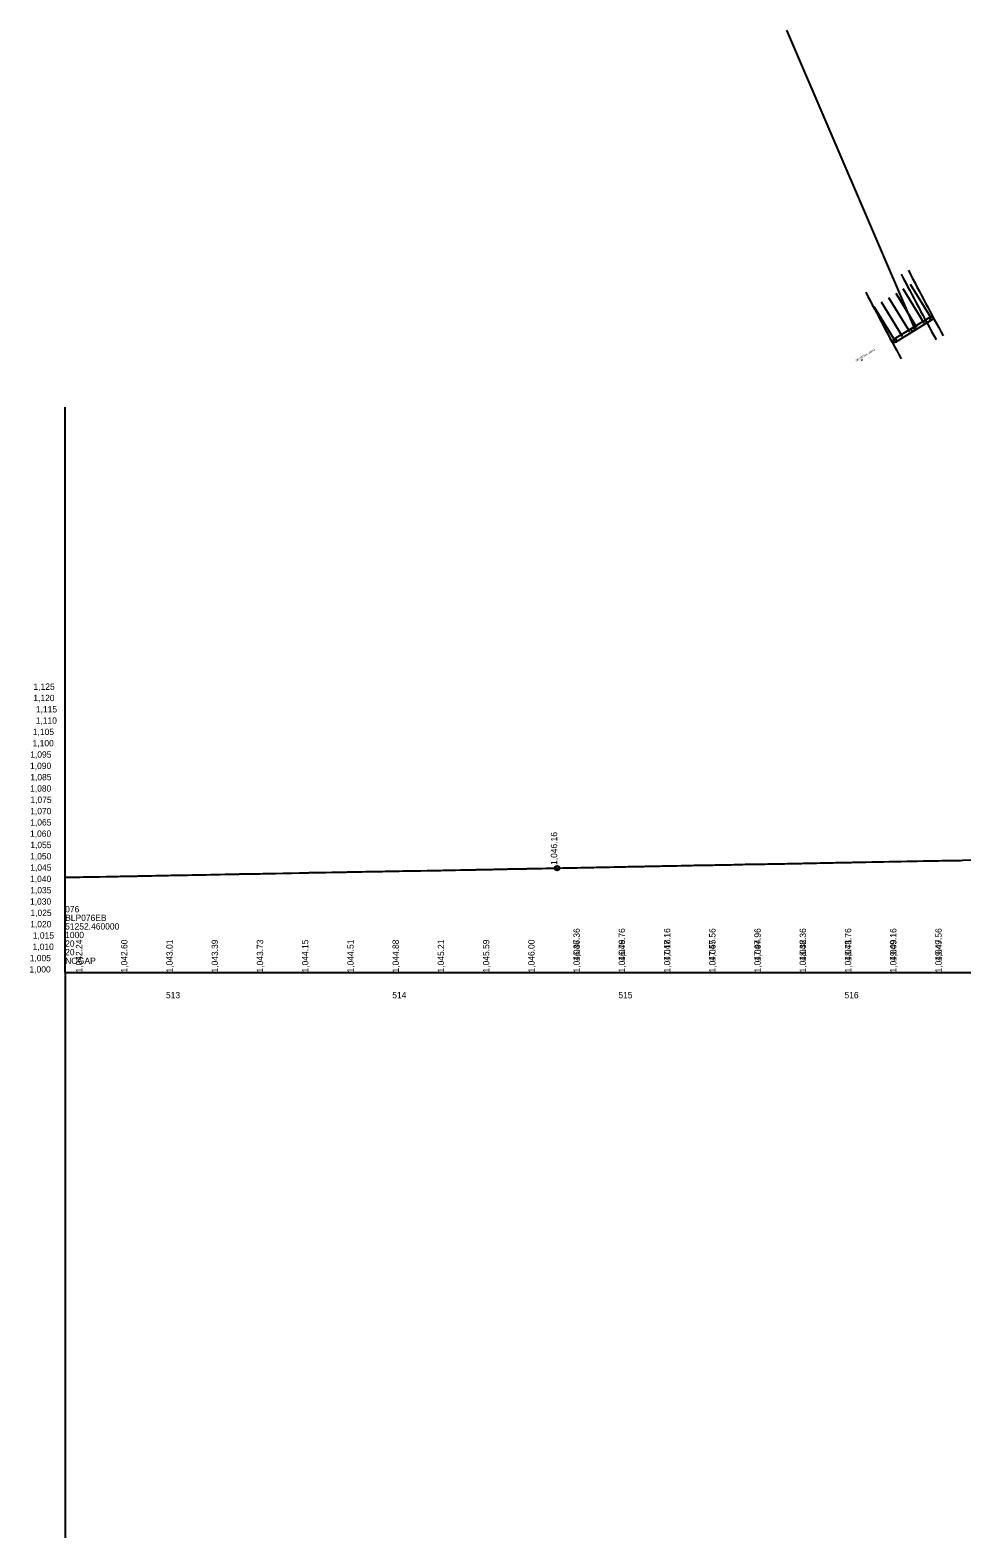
# Model space of a CAD drawing. Extents: x 2241514 to 2245530, y 509521 to 510188.
# Drawn here: x 2241514 to 2241926, y 509521 to 510188 of the extents above; entities that cross this region are included whole.
import ezdxf

# ---------------------------------------------------------------- set-up
doc = ezdxf.new("R2010")
doc.units = 0
for name, color, linetype in [('Default', 7, 'Continuous'), ('GK_Cells', 7, 'Continuous'), ('PF_P_Grade_Line', 7, 'Continuous'), ('PF_P_Sta_Elev_Text', 7, 'Continuous'), ('PF_P_Text', 7, 'Continuous'), ('PF_X_Ground_Line', 7, 'Continuous'), ('PF_X_Text', 7, 'Continuous'), ('SC_Scratch3', 7, 'Continuous')]:
    doc.layers.add(name, color=color, linetype=linetype)

msp = doc.modelspace()

# ---------------------------------------------------------------- linework, layer by layer
at = {"layer": 'GK_Cells'}
for q in [(2241529.6, 510021.03), (2245529.6, 509771.03), (2241529.6, 509521.03)]:
    msp.add_line((2241529.6, 509771.03), q, dxfattribs=at)
at = {"layer": 'PF_P_Grade_Line'}
msp.add_line((2241747.14, 509817.19), (2241977.14, 509821.8), dxfattribs=at)
at = {"layer": 'PF_P_Text'}
msp.add_circle((2241747.14, 509817.19), 1, dxfattribs=at)
at = {"layer": 'PF_X_Ground_Line'}
for points in [[(2241815.81, 509818.56), (2241816.09, 509818.57), (2241816.97, 509818.58), (2241818.02, 509818.6), (2241818.39, 509818.6), (2241818.68, 509818.61), (2241819.78, 509818.63), (2241821.49, 509818.66), (2241822.29, 509818.68), (2241823.25, 509818.71), (2241824, 509818.72), (2241825.43, 509818.76), (2241825.9, 509818.78), (2241826.36, 509818.79), (2241827.22, 509818.82), (2241828.1, 509818.84), (2241829.17, 509818.86), (2241830.27, 509818.88), (2241830.39, 509818.88), (2241831.63, 509818.9), (2241832.85, 509818.91), (2241833.66, 509818.92), (2241836.12, 509818.96), (2241836.12, 509818.96), (2241836.12, 509818.96), (2241838.15, 509818.99), (2241838.88, 509819), (2241840.31, 509819.02), (2241842.72, 509819.06), (2241842.74, 509819.06), (2241842.74, 509819.06), (2241842.79, 509819.06), (2241845.09, 509819.11), (2241845.38, 509819.12), (2241846.11, 509819.13), (2241847.26, 509819.16), (2241847.61, 509819.16), (2241849.03, 509819.18), (2241849.11, 509819.18), (2241850.08, 509819.2), (2241850.47, 509819.2), (2241852.67, 509819.25), (2241852.98, 509819.26), (2241853.23, 509819.27), (2241855.15, 509819.31), (2241856.05, 509819.33), (2241856.2, 509819.34), (2241856.7, 509819.35), (2241857.85, 509819.37), (2241858.35, 509819.38), (2241859.24, 509819.4), (2241860.23, 509819.42), (2241860.63, 509819.43), (2241860.87, 509819.43), (2241861.78, 509819.45), (2241863.4, 509819.48), (2241864.08, 509819.49), (2241864.36, 509819.5), (2241866.5, 509819.54), (2241866.63, 509819.55), (2241867.07, 509819.55), (2241868.12, 509819.57), (2241868.74, 509819.58), (2241869.13, 509819.58), (2241870.34, 509819.61), (2241870.83, 509819.62), (2241871.99, 509819.64), (2241872.4, 509819.65), (2241873.36, 509819.67), (2241873.64, 509819.68), (2241874.11, 509819.69), (2241876.86, 509819.74), (2241877.27, 509819.75), (2241877.86, 509819.77), (2241879.96, 509819.81), (2241881.06, 509819.83), (2241881.23, 509819.83), (2241881.45, 509819.84), (2241883.03, 509819.87), (2241883.68, 509819.88), (2241886.3, 509819.93), (2241886.32, 509819.93), (2241886.38, 509819.93), (2241888.9, 509819.99), (2241890.98, 509820.03), (2241891.46, 509820.03), (2241891.47, 509820.03), (2241891.47, 509820.03), (2241893.97, 509820.07), (2241894.03, 509820.07), (2241894.11, 509820.07), (2241894.31, 509820.08), (2241895.41, 509820.09), (2241895.95, 509820.1), (2241897.31, 509820.12), (2241899.01, 509820.16), (2241899.17, 509820.16), (2241899.28, 509820.17), (2241901.78, 509820.21), (2241902.1, 509820.22), (2241903.4, 509820.25)], [(2241903.4, 509820.25), (2241905.1, 509820.29), (2241905.74, 509820.31), (2241906.32, 509820.32), (2241909.11, 509820.36), (2241909.35, 509820.36), (2241909.59, 509820.37), (2241910.59, 509820.38), (2241911.83, 509820.4), (2241912.81, 509820.42), (2241913.47, 509820.43), (2241915.08, 509820.46), (2241915.75, 509820.48), (2241917.27, 509820.51), (2241918.49, 509820.53), (2241919.69, 509820.54), (2241920.1, 509820.55), (2241921.51, 509820.56), (2241922.26, 509820.56), (2241922.33, 509820.56), (2241923.94, 509820.59), (2241925.59, 509820.63), (2241926.5, 509820.66)], [(2241529.6, 509813.15), (2241530.14, 509813.15), (2241530.65, 509813.16), (2241531.71, 509813.18), (2241532.24, 509813.18), (2241533.72, 509813.21), (2241533.79, 509813.21), (2241535.74, 509813.25), (2241536.14, 509813.26), (2241537.57, 509813.28), (2241539.1, 509813.3), (2241540.88, 509813.32), (2241543.43, 509813.38), (2241544.78, 509813.4), (2241547.55, 509813.45), (2241548.19, 509813.46), (2241548.91, 509813.47), (2241549.21, 509813.48), (2241550.75, 509813.52), (2241551.53, 509813.53), (2241553.06, 509813.56), (2241553.91, 509813.58), (2241554.47, 509813.59), (2241555.36, 509813.61), (2241557.25, 509813.63), (2241558.15, 509813.65), (2241558.31, 509813.65), (2241558.47, 509813.66), (2241560, 509813.68), (2241561.02, 509813.69), (2241561.44, 509813.7), (2241562.08, 509813.71), (2241563.43, 509813.74), (2241564.49, 509813.77), (2241565.66, 509813.8), (2241565.83, 509813.8), (2241566.04, 509813.81), (2241566.81, 509813.82), (2241567.72, 509813.85), (2241569.69, 509813.9), (2241570.32, 509813.91), (2241571.44, 509813.94), (2241572.4, 509813.96), (2241573.64, 509813.98), (2241575.03, 509814), (2241575.29, 509814), (2241576.38, 509814.03), (2241577.61, 509814.05), (2241577.94, 509814.06), (2241579.21, 509814.08), (2241581.31, 509814.11), (2241581.69, 509814.11), (2241582.48, 509814.12), (2241583.09, 509814.13), (2241583.73, 509814.14), (2241585.77, 509814.17), (2241586.61, 509814.18), (2241587.17, 509814.19), (2241587.85, 509814.2), (2241589.77, 509814.24), (2241590.4, 509814.25), (2241591.96, 509814.29), (2241594.01, 509814.34), (2241594.76, 509814.36), (2241595.27, 509814.38), (2241597.02, 509814.42), (2241597.38, 509814.43), (2241598.2, 509814.44), (2241600.39, 509814.48), (2241600.91, 509814.49), (2241601.58, 509814.5), (2241601.89, 509814.5), (2241602.84, 509814.52), (2241603.02, 509814.53), (2241603.9, 509814.54), (2241605.84, 509814.58), (2241606.45, 509814.59), (2241606.75, 509814.6), (2241607.55, 509814.61), (2241609.43, 509814.64), (2241610.16, 509814.63), (2241610.32, 509814.63), (2241610.82, 509814.64), (2241613.66, 509814.66), (2241615.66, 509814.73), (2241617.04, 509814.76), (2241617.85, 509814.77), (2241618.15, 509814.78), (2241620.48, 509814.82), (2241621.94, 509814.85), (2241622.55, 509814.87), (2241625.85, 509814.94), (2241625.96, 509814.94), (2241625.97, 509814.94), (2241626.01, 509814.94), (2241626.04, 509814.95), (2241627.36, 509814.98), (2241628.84, 509815.01), (2241629.33, 509815.01), (2241629.43, 509815.02), (2241629.58, 509815.02)], [(2241629.58, 509815.02), (2241629.74, 509815.02), (2241633.28, 509815.09), (2241633.46, 509815.1), (2241635.01, 509815.13), (2241637.08, 509815.18), (2241637.54, 509815.19), (2241639.14, 509815.23), (2241640.68, 509815.26), (2241641.84, 509815.29), (2241643.68, 509815.31), (2241644.67, 509815.33), (2241644.91, 509815.33), (2241647.45, 509815.35), (2241647.62, 509815.35), (2241647.77, 509815.35), (2241647.98, 509815.36), (2241648.45, 509815.37), (2241649.81, 509815.38), (2241651.35, 509815.41), (2241651.55, 509815.42), (2241652.04, 509815.43), (2241653.49, 509815.46), (2241653.8, 509815.47), (2241654.5, 509815.49), (2241656.22, 509815.53), (2241657.11, 509815.54), (2241657.89, 509815.56), (2241658.08, 509815.56), (2241659.98, 509815.59), (2241660.14, 509815.6), (2241660.54, 509815.61), (2241660.92, 509815.61), (2241662.47, 509815.63), (2241663.33, 509815.64), (2241664.29, 509815.66), (2241665.55, 509815.68), (2241666.09, 509815.69), (2241667.8, 509815.72), (2241668.43, 509815.73), (2241669.88, 509815.76), (2241671.03, 509815.79), (2241672.14, 509815.81), (2241672.56, 509815.82), (2241673.22, 509815.83), (2241674.32, 509815.86), (2241674.94, 509815.87), (2241675.48, 509815.88), (2241676.69, 509815.9), (2241676.72, 509815.9), (2241676.77, 509815.9), (2241677.25, 509815.91), (2241678.86, 509815.93), (2241679, 509815.94), (2241680.92, 509815.96), (2241680.96, 509815.96), (2241680.96, 509815.96), (2241682.77, 509815.98), (2241685.1, 509816.01), (2241685.14, 509816.01), (2241685.16, 509816.01), (2241686.35, 509816.04), (2241686.39, 509816.04), (2241686.43, 509816.04), (2241686.71, 509816.05), (2241689.71, 509816.12), (2241690.39, 509816.12), (2241691.3, 509816.13), (2241692.75, 509816.14), (2241693.15, 509816.15), (2241693.36, 509816.15), (2241695.44, 509816.2), (2241695.69, 509816.2), (2241696.67, 509816.23), (2241697.63, 509816.25), (2241697.94, 509816.26), (2241700.02, 509816.31), (2241700.66, 509816.33), (2241700.86, 509816.33), (2241702.22, 509816.36), (2241702.23, 509816.36), (2241702.23, 509816.36), (2241702.23, 509816.36), (2241704.37, 509816.39), (2241706.37, 509816.42), (2241706.5, 509816.42), (2241706.58, 509816.42), (2241706.89, 509816.43), (2241709.58, 509816.47), (2241710.61, 509816.5), (2241710.96, 509816.5), (2241711.33, 509816.51), (2241713.29, 509816.55), (2241713.44, 509816.56), (2241714.89, 509816.58), (2241715.3, 509816.58), (2241715.5, 509816.59), (2241716.96, 509816.62), (2241717.97, 509816.64), (2241718.55, 509816.65), (2241719.34, 509816.67)], [(2241719.34, 509816.67), (2241720.46, 509816.7), (2241721.47, 509816.73), (2241722.2, 509816.74), (2241722.97, 509816.75), (2241723.34, 509816.76), (2241724.17, 509816.78), (2241724.89, 509816.8), (2241725.46, 509816.81), (2241726.82, 509816.82), (2241727.96, 509816.84), (2241728.26, 509816.84), (2241729.91, 509816.87), (2241730.88, 509816.89), (2241732.53, 509816.92), (2241732.68, 509816.93), (2241733.66, 509816.95), (2241733.67, 509816.95), (2241733.82, 509816.96), (2241737.61, 509817.04), (2241737.68, 509817.05), (2241737.8, 509817.05), (2241739.13, 509817.06), (2241740.64, 509817.08), (2241742.24, 509817.1), (2241743.01, 509817.11), (2241744.96, 509817.14), (2241745.52, 509817.15), (2241747.27, 509817.19), (2241747.34, 509817.19), (2241749.65, 509817.25), (2241749.82, 509817.26), (2241750.01, 509817.26), (2241752.51, 509817.32), (2241753.44, 509817.34), (2241754.65, 509817.36), (2241755.93, 509817.38), (2241755.94, 509817.38), (2241755.94, 509817.38), (2241757.61, 509817.41), (2241758.92, 509817.43), (2241759.78, 509817.45), (2241760.31, 509817.46), (2241761.59, 509817.48), (2241762.29, 509817.5), (2241763.31, 509817.52), (2241764.39, 509817.55), (2241765.02, 509817.56), (2241766.77, 509817.59), (2241767.84, 509817.61), (2241768.94, 509817.64), (2241770.36, 509817.67), (2241772.38, 509817.71), (2241772.76, 509817.72), (2241773.87, 509817.75), (2241776.81, 509817.82), (2241777.16, 509817.82), (2241777.54, 509817.83), (2241778.6, 509817.84), (2241779.51, 509817.85), (2241781.3, 509817.87), (2241782.1, 509817.89), (2241784.47, 509817.94), (2241785.6, 509817.97), (2241786.23, 509817.99), (2241787, 509818.01), (2241788.62, 509818.05), (2241789.93, 509818.07), (2241790.09, 509818.08), (2241790.22, 509818.08), (2241791.2, 509818.1), (2241792.15, 509818.12), (2241792.54, 509818.13), (2241793.41, 509818.15), (2241794.26, 509818.16), (2241795.24, 509818.18), (2241795.52, 509818.19), (2241795.67, 509818.19), (2241797, 509818.21), (2241797.67, 509818.23), (2241799.68, 509818.26), (2241800.25, 509818.27), (2241801.9, 509818.3), (2241802.57, 509818.31), (2241804.07, 509818.34), (2241804.53, 509818.35), (2241804.78, 509818.36), (2241805.15, 509818.37), (2241806.81, 509818.41), (2241807.64, 509818.44), (2241807.97, 509818.44), (2241808.44, 509818.45), (2241809.46, 509818.48), (2241810.24, 509818.5), (2241810.69, 509818.5), (2241812.59, 509818.53), (2241812.66, 509818.53), (2241813.26, 509818.54), (2241814.12, 509818.55), (2241815.49, 509818.56), (2241815.81, 509818.56)]]:
    msp.add_lwpolyline(points, dxfattribs=at)
at = {"layer": 'SC_Scratch3'}
for p, q in [((2241848.54, 510187.75), (2241905.1, 510055.82)), ((2241900.03, 510073.46), (2241909.27, 510058.37)), ((2241903.24, 510075.43), (2241912.48, 510060.33)), ((2241890.41, 510067.58), (2241899.65, 510052.48)), ((2241893.62, 510069.54), (2241902.86, 510054.45)), ((2241896.83, 510071.5), (2241906.07, 510056.41)), ((2241887.21, 510065.61), (2241896.45, 510050.52)), ((2241895.95, 510051.09), (2241912.2, 510061.04)), ((2241896.73, 510049.81), (2241912.98, 510059.76)), ((2241881.62, 510042.07), (2241881.88, 510041.66))]:
    msp.add_line(p, q, dxfattribs=at)
for centre in [(2241912.59, 510060.4), (2241904.46, 510055.43), (2241896.34, 510050.45)]:
    msp.add_circle(centre, 0.75, dxfattribs=at)
for radius in [1145.87, 1142.29, 1163.46]:
    msp.add_arc((2242918.34, 510603.8), radius, 207.20615, 208.84892, dxfattribs=at)

# ---------------------------------------------------------------- texts
at = {"layer": 'Default'}
for s, p in [('1,095', (2241514.15, 509866.03)), ('1,090', (2241514.06, 509861.03)), ('1,080', (2241514.11, 509851.03)), ('1,085', (2241514.19, 509856.03)), ('1,075', (2241514.24, 509846.03)), ('1,070', (2241514.15, 509841.03)), ('1,060', (2241514.06, 509831.03)), ('1,065', (2241514.15, 509836.03)), ('1,055', (2241514.19, 509826.03)), ('1,050', (2241514.11, 509821.03)), ('1,040', (2241514.08, 509811.03)), ('1,045', (2241514.17, 509816.03)), ('1,035', (2241514.15, 509806.03)), ('1,030', (2241514.06, 509801.03)), ('1,020', (2241514.15, 509791.03)), ('1,025', (2241514.24, 509796.03)), ('1,015', (2241515.3, 509786.03)), ('1,010', (2241515.21, 509781.03)), ('1,000', (2241513.84, 509771.03)), ('1,005', (2241513.93, 509776.03))]:
    msp.add_text(s, height=2.8, dxfattribs=at).set_placement(p)
at = {"layer": 'GK_Cells'}
for s, p in [('076', (2241529.6, 509797.63)), ('51252.460000', (2241529.6, 509790.03)), ('BLP076EB', (2241529.6, 509793.83)), ('1000', (2241529.6, 509786.23)), ('20', (2241529.6, 509782.43)), ('20', (2241529.6, 509778.63)), ('NOGAP', (2241529.6, 509774.83))]:
    msp.add_text(s, height=2.8, dxfattribs=at).set_placement(p)
at = {"layer": 'PF_P_Sta_Elev_Text'}
for s, p in [('1,120', (2241515.52, 509891.03)), ('1,125', (2241515.61, 509896.03)), ('1,115', (2241516.67, 509886.03)), ('1,110', (2241516.58, 509881.03)), ('1,100', (2241515.21, 509871.03)), ('1,105', (2241515.3, 509876.03)), ('1,095', (2241514.15, 509866.03)), ('1,090', (2241514.06, 509861.03)), ('1,080', (2241514.11, 509851.03)), ('1,085', (2241514.19, 509856.03)), ('1,075', (2241514.24, 509846.03)), ('1,070', (2241514.15, 509841.03)), ('1,060', (2241514.06, 509831.03)), ('1,065', (2241514.15, 509836.03)), ('1,055', (2241514.19, 509826.03)), ('1,050', (2241514.11, 509821.03)), ('1,040', (2241514.08, 509811.03)), ('1,045', (2241514.17, 509816.03)), ('1,035', (2241514.15, 509806.03)), ('1,030', (2241514.06, 509801.03)), ('1,020', (2241514.15, 509791.03)), ('1,025', (2241514.24, 509796.03)), ('1,015', (2241515.3, 509786.03)), ('1,010', (2241515.21, 509781.03)), ('1,000', (2241513.84, 509771.03)), ('1,005', (2241513.93, 509776.03)), ('513', (2241574.18, 509759.63)), ('514', (2241674.23, 509759.63)), ('515', (2241774.2, 509759.63)), ('516', (2241874.18, 509759.63))]:
    msp.add_text(s, height=2.8, dxfattribs=at).set_placement(p)
at = {"layer": 'PF_P_Text'}
for s, p in [('1,046.16', (2241747.14, 509818.59)), ('1,046.36', (2241757.14, 509776.03)), ('1,046.76', (2241777.14, 509776.03)), ('1,047.16', (2241797.14, 509776.03)), ('1,047.56', (2241817.14, 509776.03)), ('1,047.96', (2241837.14, 509776.03)), ('1,048.36', (2241857.14, 509776.03)), ('1,048.76', (2241877.14, 509776.03)), ('1,049.16', (2241897.14, 509776.03)), ('1,049.56', (2241917.14, 509776.03))]:
    msp.add_text(s, height=2.8, rotation=90, dxfattribs=at).set_placement(p)
at = {"layer": 'PF_X_Text'}
for s, p in [('1,042.24', (2241537.14, 509771.03)), ('1,042.60', (2241557.14, 509771.03)), ('1,043.01', (2241577.14, 509771.03)), ('1,043.39', (2241597.14, 509771.03)), ('1,043.73', (2241617.14, 509771.03)), ('1,044.15', (2241637.14, 509771.03)), ('1,044.51', (2241657.14, 509771.03)), ('1,044.88', (2241677.14, 509771.03)), ('1,045.21', (2241697.14, 509771.03)), ('1,045.59', (2241717.14, 509771.03)), ('1,046.00', (2241737.14, 509771.03)), ('1,046.37', (2241757.14, 509771.03)), ('1,046.79', (2241777.14, 509771.03)), ('1,047.18', (2241797.14, 509771.03)), ('1,047.55', (2241817.14, 509771.03)), ('1,047.94', (2241837.14, 509771.03)), ('1,048.32', (2241857.14, 509771.03)), ('1,048.71', (2241877.14, 509771.03)), ('1,049.09', (2241897.14, 509771.03)), ('1,049.47', (2241917.14, 509771.03))]:
    msp.add_text(s, height=2.8, rotation=90, dxfattribs=at).set_placement(p)
at = {"layer": 'SC_Scratch3'}
msp.add_text('432+00 (ex. plans)', height=0.875, rotation=31.47561, dxfattribs=at).set_placement((2241879.17, 510041.02))

doc.saveas('drawing.dxf')
